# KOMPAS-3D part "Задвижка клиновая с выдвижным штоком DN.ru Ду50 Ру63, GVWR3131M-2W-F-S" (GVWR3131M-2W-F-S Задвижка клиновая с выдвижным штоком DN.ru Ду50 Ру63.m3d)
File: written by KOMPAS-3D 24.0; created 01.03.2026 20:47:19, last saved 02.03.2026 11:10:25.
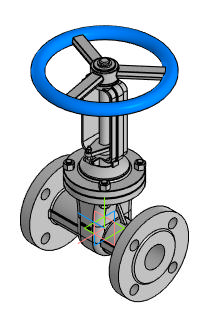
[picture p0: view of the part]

Document properties: Автор: R2D2; Полное имя файла: D:\Работа\проверка\Алишер\задвижки клиновые\GVWR3131M-2W-F-S Задвижка клиновая с выдвижным штоком DN.ru Ду50-200 Ру63\DN50\GVWR3131M-2W-F-S Задвижка клиновая с выдвижным штоком DN.ru Ду50 Ру63.m3d

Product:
- Part/product: Задвижка клиновая с выдвижным штоком DN.ru Ду50 Ру63  | designation GVWR3131M-2W-F-S
    Масса: 25.5
    Раздел спецификации: Прочие изделия
    Примечание: D040-07393
    additional columns: D040-07393

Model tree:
1. Операция без истории:2

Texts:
  GVWR3131M-2W-F-S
